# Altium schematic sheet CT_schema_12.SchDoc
size 519 x 434 mm
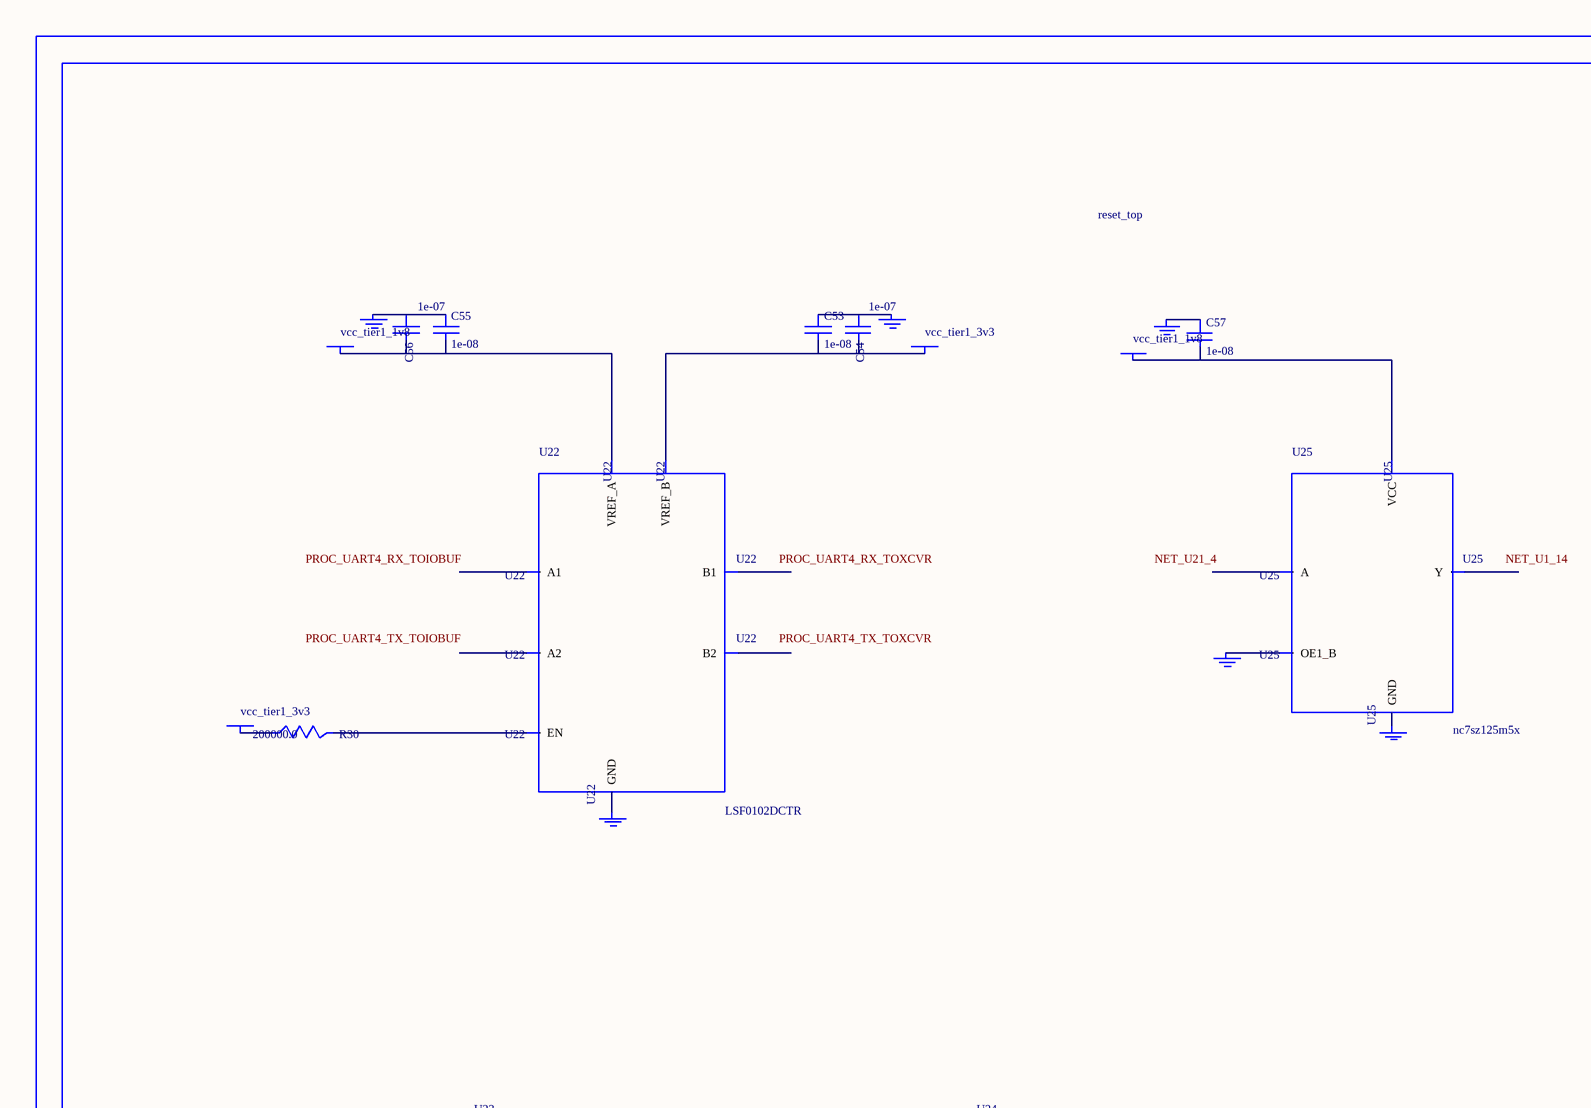
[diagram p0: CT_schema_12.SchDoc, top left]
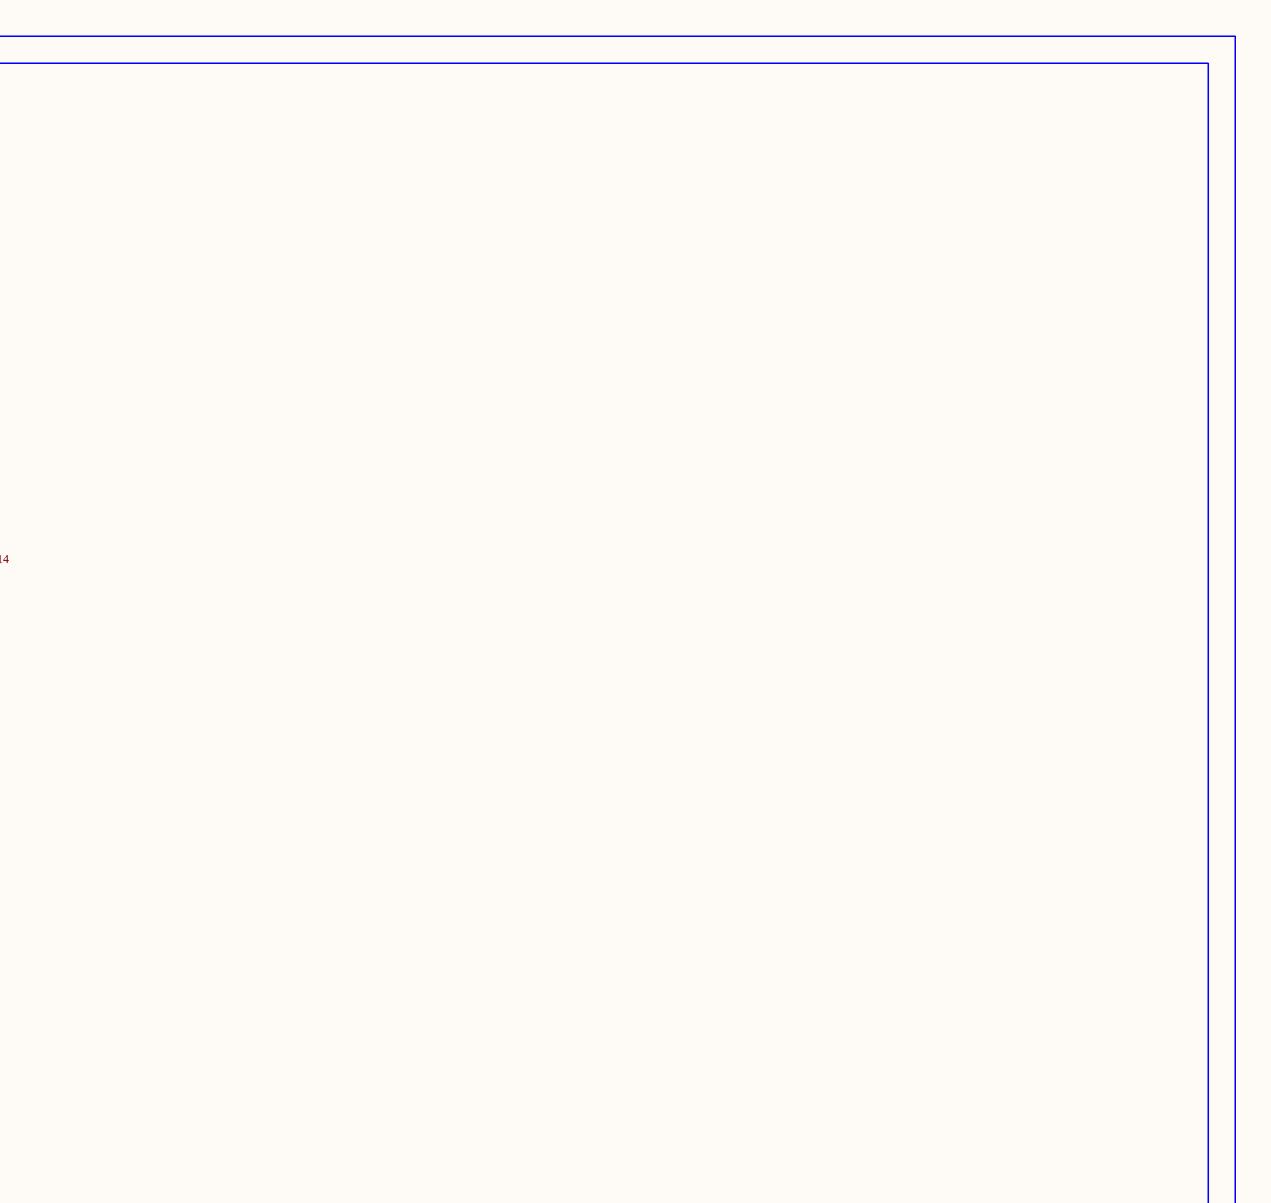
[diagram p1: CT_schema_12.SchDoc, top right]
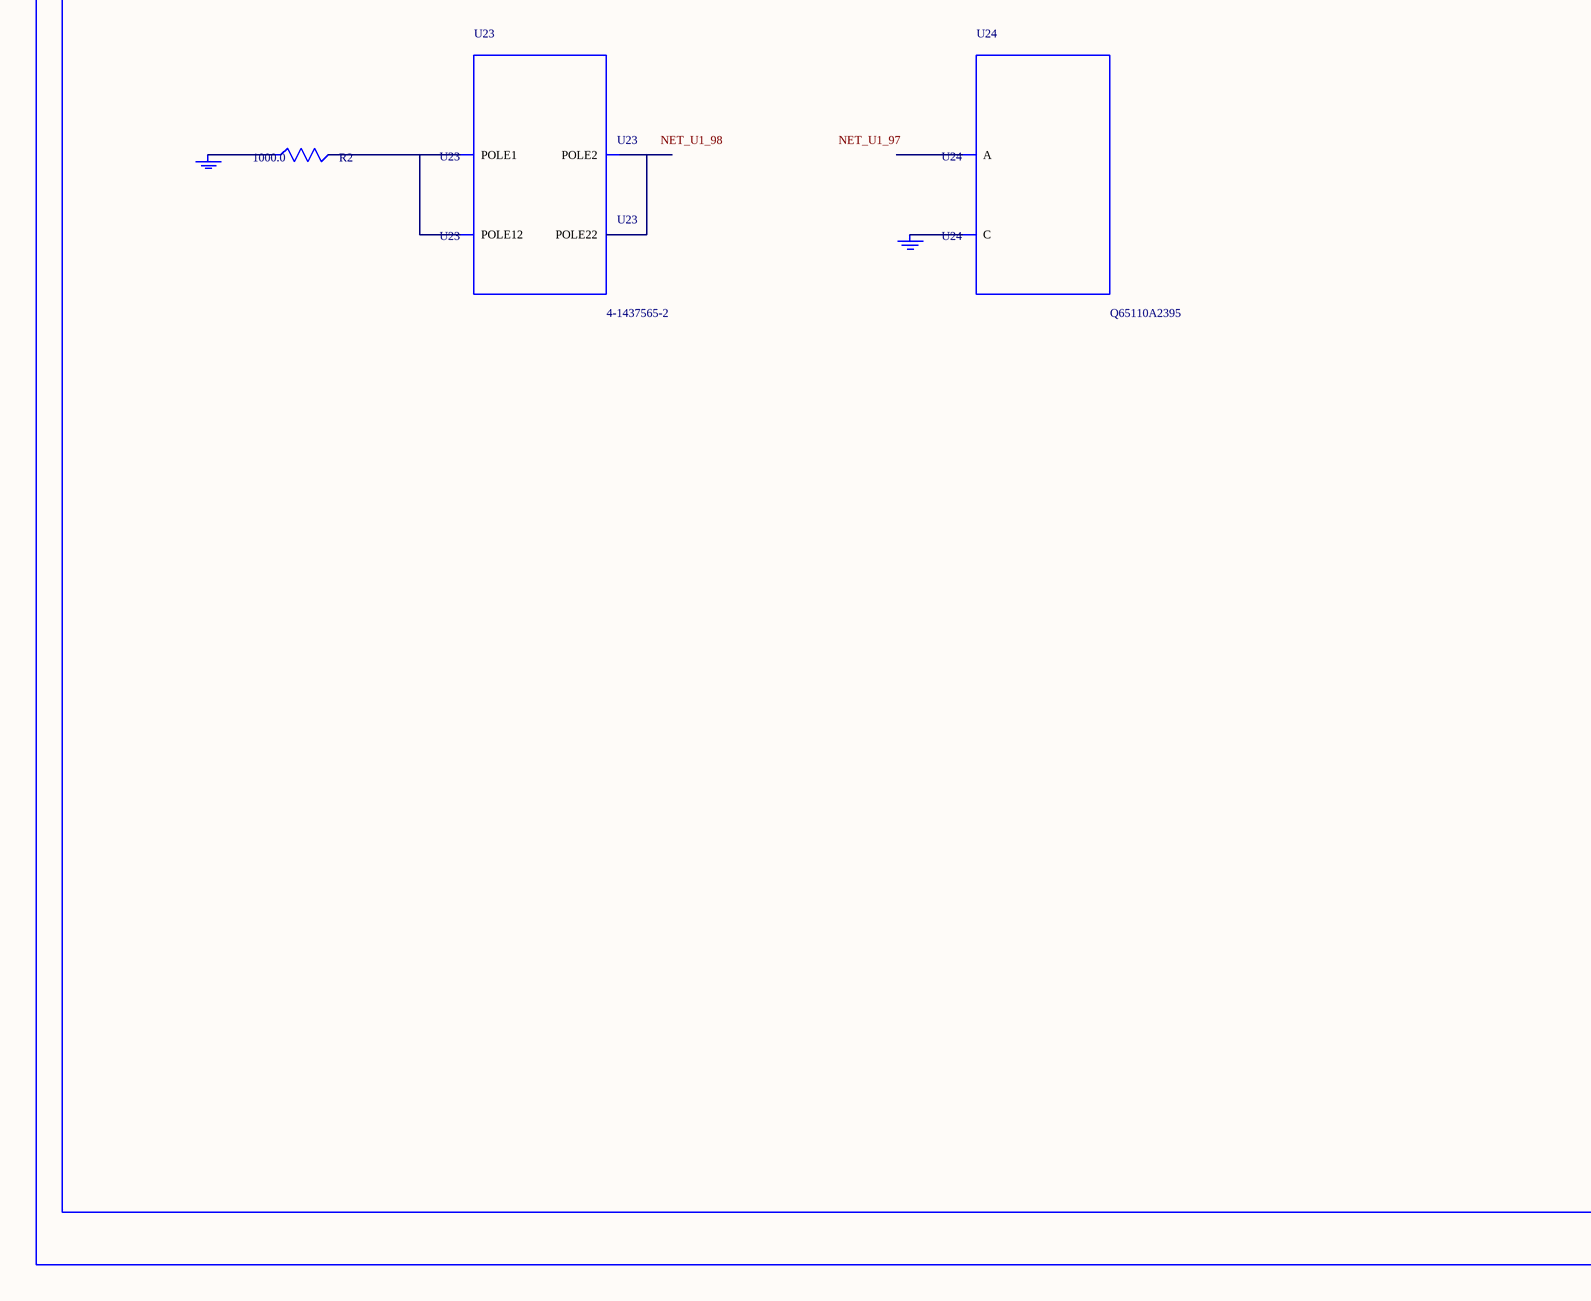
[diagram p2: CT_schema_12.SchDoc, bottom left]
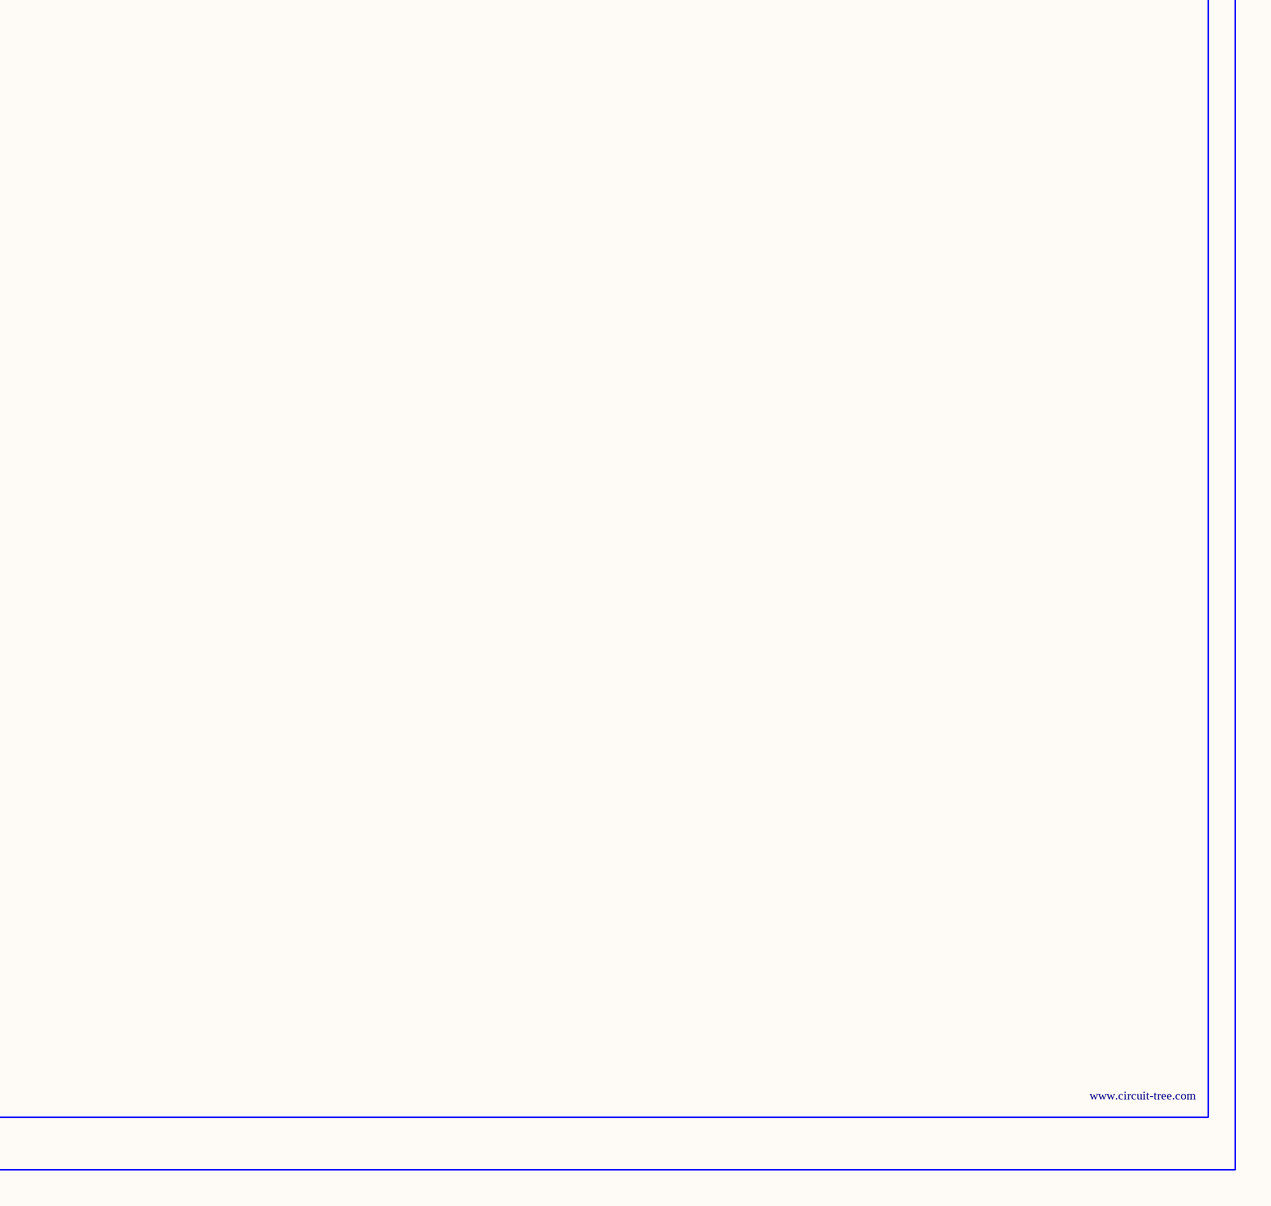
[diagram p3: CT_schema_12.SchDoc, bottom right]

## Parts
BORDER11  (no value)
C53  1e-08  [C0402]
C54  1e-07  [C0402]
C55  1e-08  [C0402]
C56  1e-07  [C0402]
C57  1e-08  [C0402]
GND_INSTANCE_11_0  (no value)
GND_INSTANCE_11_1  (no value)
GND_INSTANCE_11_2  (no value)
GND_INSTANCE_11_3  (no value)
GND_INSTANCE_11_4  (no value)
GND_INSTANCE_11_5  (no value)
GND_INSTANCE_11_6  (no value)
GND_INSTANCE_11_7  (no value)
POWER_INSTANCE_11_0  vcc_tier1_1v8
POWER_INSTANCE_11_1  vcc_tier1_3v3
POWER_INSTANCE_11_2  vcc_tier1_3v3
POWER_INSTANCE_11_3  vcc_tier1_1v8
R2  1000.0  [R0603]
R30  200000.0  [R0603]
U22  LSF0102DCTR  [DCU0008A_N]
U23  4-1437565-2  [SW_4-1437565-2]
U24  Q65110A2395  [LGM67K-G1J2-24-Z]
U25  nc7sz125m5x  [NC7SZ125M5X]

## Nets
NetC53_1: C53.1 C54.1 GND_INSTANCE_11_1.0(GND)
NetC53_2: C53.2 C54.2 POWER_INSTANCE_11_1.0(PWR) U22.7(VREF_B)
NetC55_1: C55.1 C56.1 GND_INSTANCE_11_0.0(GND)
NetC55_2: C55.2 C56.2 POWER_INSTANCE_11_0.0(PWR) U22.2(VREF_A)
NetC57_1: C57.1 GND_INSTANCE_11_5.0(GND)
NetC57_2: C57.2 POWER_INSTANCE_11_3.0(PWR) U25.5(VCC)
NetGND_INSTANCE_11_2_0: GND_INSTANCE_11_2.0(GND) U22.1(GND)
NetGND_INSTANCE_11_3_0: GND_INSTANCE_11_3.0(GND) R2.1
NetGND_INSTANCE_11_4_0: GND_INSTANCE_11_4.0(GND) U24.C
NetGND_INSTANCE_11_6_0: GND_INSTANCE_11_6.0(GND) U25.1(OE1_B)
NetGND_INSTANCE_11_7_0: GND_INSTANCE_11_7.0(GND) U25.3(GND)
NetPOWER_INSTANCE_11_2_0: POWER_INSTANCE_11_2.0(PWR) R30.1
NetR2_2: R2.2 U23.1(POLE1) U23.2(POLE12)
NetR30_2: R30.2 U22.8(EN)
NetU23_3: U23.3(POLE2) U23.4(POLE22)

Not connected (* = marked no-connect by the designer): U22 3(A1) 4(A2) 5(B2) 6(B1); U24 A; U25 2(A) 4(Y)

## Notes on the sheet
- Labels drawn without touching a wire or pin: NET_U1_14, NET_U1_97, NET_U1_98, NET_U21_4, PROC_UART4_RX_TOIOBUF, PROC_UART4_RX_TOXCVR, PROC_UART4_TX_TOIOBUF, PROC_UART4_TX_TOXCVR

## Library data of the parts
BORDER11 = BORDER_PAGE11
C53 C55 C57 = C0402C103K3RAC
C54 C56 = C0402C104K3RACTU
GND_INSTANCE_11_0-GND_INSTANCE_11_7 = GND
POWER_INSTANCE_11_0-POWER_INSTANCE_11_3 = PWR
R2 = RC0603JR-071KL
R30 = RC0603JR-07200KL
